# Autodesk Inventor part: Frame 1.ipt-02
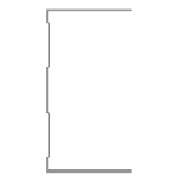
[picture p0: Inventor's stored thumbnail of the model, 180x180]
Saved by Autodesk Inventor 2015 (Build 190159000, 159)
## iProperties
IsCustomPart: 1
Created: 2015-04
Part Number: Frame 1.ipt-02
Material: Aluminum 6061
Description: Kévin Novo
Document SubType Name: Modeling
Standard: Kevin
Designer: suporte
Standards Organization: Kevin
Language: en-US
Size Designation: (Unnamed 2)
Categories: <MemberInstance><Categories><Category DisplayName="Structural Shapes" InternalName="089c4875-fa83-4c05-b084-43b9cc11f5ed" Mnemonic="GRDR"><CategoryParameter Dis
Density: 2.7 g/cm^3
Appearance: Aluminum - Flat
_CCFamilyMember: 2
_CCFamilyDisplayName: Kévin - Kévin Novo
_FrameMemberDoc: Frame Member File
_Version: 15.0.0
_GetPNFromCC: 1
G_W: 50,000 mm
G_H: 75,000 mm
G_L: 1042,320 mm
+C6D07C4E-F784-4905-9E85-D001DAC4732C+CUTDETAIL2: Miter 67,49 deg
+B79A86F4-2235-41DC-B6D9-DBBE6F4256FF+CUTDETAIL3: Cut
Author: suporte
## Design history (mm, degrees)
node "Start Plane"
node "End Plane"
sketch "Sketch"
  geometry: L1 (24.7, 37.5)-(24.7, 36.9); L2 (24.7, 36.9)-(-24.7, 36.9); L3 (-24.7, -36.9)-(24.7, -36.9); L4 (24.7, -36.9)-(24.7, -37.5); L5 (24.7, -37.5)-(-25.3, -37.5); L6 (-25.3, 37.5)-(24.7, 37.5); L7 (-24.7, 36.9)-(-24.7, 31.9); L8 (-24.7, 31.9)-(-23.3, 30.5); L9 (-23.3, 30.5)-(-23.3, 10.934); L10 (-23.3, 10.934)-(-24.7, 9.534); L11 (-24.7, 9.534)-(-24.7, -9.534); L12 (-24.7, -9.534)-(-23.3, -10.934); L13 (-23.3, -10.934)-(-23.3, -30.5); L14 (-23.3, -30.5)-(-24.7, -31.9); L15 (-24.7, -31.9)-(-24.7, -36.9); L16 (-25.3, -37.5)-(-25.3, -31.651); L17 (-25.3, -31.651)-(-23.9, -30.251); L18 (-23.9, -30.251)-(-23.9, -11.183); L19 (-23.9, -11.183)-(-25.3, -9.783); L20 (-25.3, -9.783)-(-25.3, 9.783); L21 (-25.3, 9.783)-(-23.9, 11.183); L22 (-23.9, 11.183)-(-23.9, 30.251); L23 (-23.9, 30.251)-(-25.3, 31.651); L24 (-25.3, 31.651)-(-25.3, 37.5); L25 (-25.3, 0)-(30.37, 0); 3 further points
  constraints: 50 end point, 10 point on line, 9 parallel, 5 perpendicular, 4 equal length, 3 midpoint, 3 vertical, 2 vertical alignment, 1 collinear, 1 horizontal, 1 horizontal alignment
  dimensions: "d3" = 0.6 distance of L1.start L1.end (= d6); "d5" = 75 distance between parallel lines of L5 L6; "d6" = 0.6 distance between parallel lines of L24 L7 (= d8); "d7" = 0.6 distance between parallel lines of L8 L23 (= d8); "d8" = 0.6 distance between parallel lines of L22 L9 (= d12); "Espessura" = 0.6 distance between parallel lines of L17 L14; "d10" = 0.6 distance between parallel lines of L13 L18 (= Espessura); "d11" = 0.6 distance between parallel lines of L12 L19 (= Espessura); "d12" = 0.6 distance between parallel lines of L21 L10 (= d11); "d13" = 5 distance of L2.end L7.end; "d15" = 135 deg angle of L9 L8; "d16" = 2 distance between parallel lines of L24 L9; "d17" = 50 distance of L6.start L1.start
extrude "Body" join sketch "Sketch" stored distance "d24" = 0.13; taper "d25" = 0 deg
node "Driven Length"
  sketch "Sketch10"
    geometry: L1 (0, 0)-(10, 0) reference
    constraints: 2 end point, 1 horizontal
  workplane "Work Plane7"
  sketch "Sketch11"
    geometry: L1 (-2, 12.5)-(12, 12.5) reference; L2 (-2, 1054.82)-(12, 1054.82) reference
    dimensions: "d27" = 1042.31978 distance between parallel lines of L1 L2 (derived)
workplane "Work Plane9"
split "Split2"
workplane "Work Plane10"
split "Split3"
body "Solid1"
other parameters: "tamanho" = 1018.55826, "G_OFFSET_START" = -12.5 [user parameter; used in 1 equation term], "G_OFFSET_END" = 36.26152 [user parameter; used in 1 equation term], "d22" = 12.5 (= -G_OFFSET_START), "d23" = 1054.81978 (= tamanho + G_OFFSET_END), "G_L" = 1042.31978 (= d27) [user parameter], "d34" = 90 deg
